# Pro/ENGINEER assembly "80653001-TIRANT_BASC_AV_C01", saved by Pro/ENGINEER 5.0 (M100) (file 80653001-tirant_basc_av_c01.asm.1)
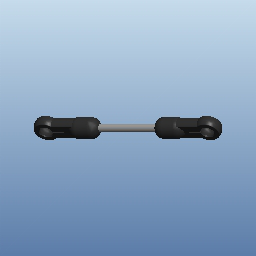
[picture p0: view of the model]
Units: millimeter Newton Second (mmNs); MM, TONNE, HOURS

Other components: 80022001-CHAPE_STD-DR_C01, 80465046-TIRANT_ACIER_LONG_C01, 80022001-CHAPE_STD-DR_C01

Other named items: A-DROITE, A-DESSUS, A-FACE, A-R0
